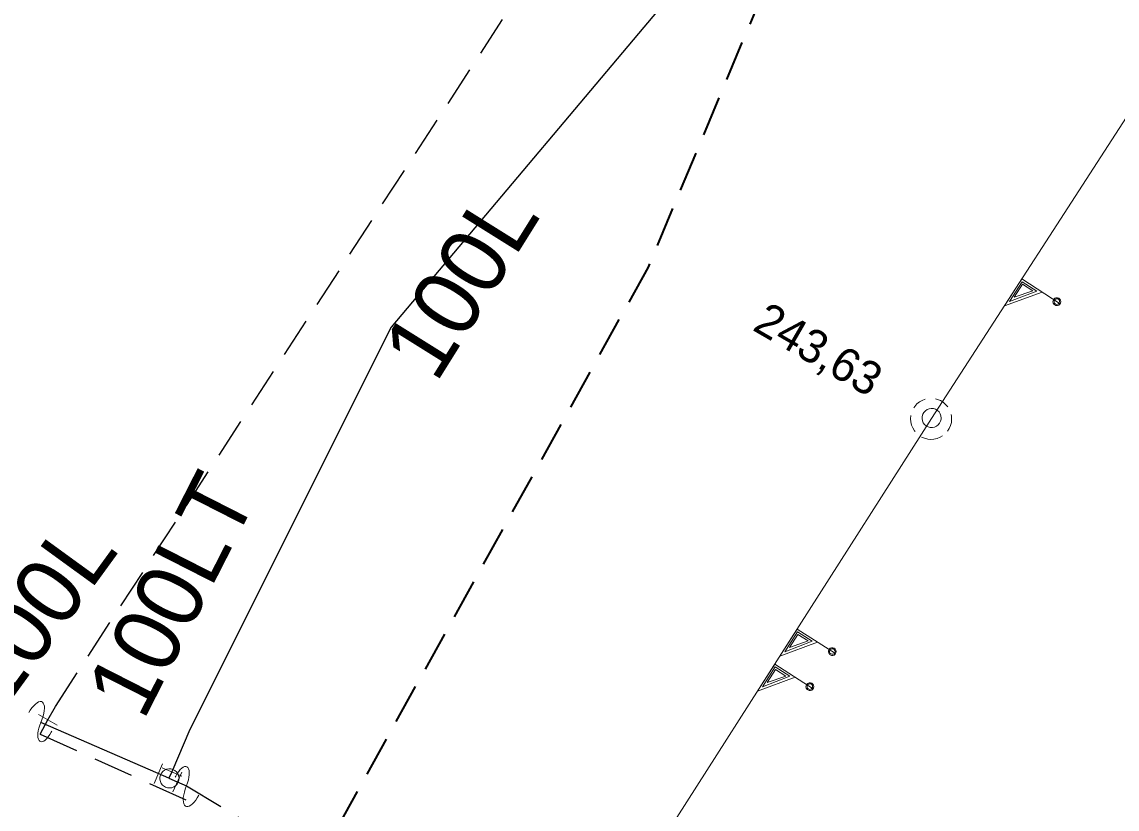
# Model space of a CAD drawing. Extents: x -735085 to -733500, y -1044153 to -1043402.
# Drawn here: x -734690.58 to -734664.28, y -1043609.34 to -1043590.44 of the extents above; entities that cross this region are included whole.
import ezdxf

# ---------------------------------------------------------------- set-up
doc = ezdxf.new("R2010")
doc.units = 0
doc.header["$LTSCALE"] = 0.32
doc.linetypes.add('MEDIUM_DASHED', pattern=[4.5, 3, -1.5])
doc.layers.add('15', color=7, linetype='Continuous')
doc.layers.add('16', color=7, linetype='Continuous')
for name, color, linetype, lineweight in [('18', 7, 'Continuous', 13), ('20', 7, 'Continuous', 13), ('8', 7, 'Continuous', 13)]:
    doc.layers.add(name, color=color, linetype=linetype, lineweight=lineweight)

msp = doc.modelspace()

# ---------------------------------------------------------------- linework, layer by layer
at = {"layer": '18'}
for points in [[(-734665.652, -1043597.204), (-734666.572, -1043596.609), (-734666.99, -1043597.257), (-734666.086, -1043596.923)], [(-734666.214, -1043596.901), (-734666.563, -1043596.675), (-734666.871, -1043597.151), (-734666.212, -1043596.902)], [(-734666.309, -1043596.896), (-734666.554, -1043596.737), (-734666.756, -1043597.049), (-734666.309, -1043596.895)], [(-734668.892, -1043599.497), (-734668.963, -1043599.525), (-734669.029, -1043599.564), (-734669.09, -1043599.612), (-734669.141, -1043599.669), (-734669.164, -1043599.703)], [(-734668.35, -1043599.68), (-734668.401, -1043599.622), (-734668.458, -1043599.572), (-734668.524, -1043599.531), (-734668.595, -1043599.502), (-734668.644, -1043599.488)], [(-734669.237, -1043599.889), (-734669.242, -1043599.966), (-734669.237, -1043600.043), (-734669.22, -1043600.118), (-734669.191, -1043600.189), (-734669.151, -1043600.255), (-734669.136, -1043600.277)], [(-734668.355, -1043600.266), (-734668.315, -1043600.201), (-734668.284, -1043600.131), (-734668.264, -1043600.056), (-734668.257, -1043599.98), (-734668.262, -1043599.903), (-734668.267, -1043599.868)], [(-734668.978, -1043600.406), (-734668.909, -1043600.437), (-734668.833, -1043600.456), (-734668.757, -1043600.463), (-734668.681, -1043600.458), (-734668.605, -1043600.441), (-734668.534, -1043600.413), (-734668.473, -1043600.378)], [(-734671.044, -1043605.608), (-734671.967, -1043605.019), (-734672.382, -1043605.669), (-734671.48, -1043605.33)], [(-734671.607, -1043605.309), (-734671.958, -1043605.085), (-734672.263, -1043605.562), (-734671.606, -1043605.31)], [(-734671.703, -1043605.304), (-734671.949, -1043605.147), (-734672.148, -1043605.46), (-734671.702, -1043605.303)], [(-734671.582, -1043606.451), (-734672.505, -1043605.862), (-734672.92, -1043606.512), (-734672.018, -1043606.173)], [(-734672.145, -1043606.152), (-734672.496, -1043605.928), (-734672.801, -1043606.405), (-734672.144, -1043606.153)], [(-734672.241, -1043606.147), (-734672.487, -1043605.99), (-734672.686, -1043606.303), (-734672.24, -1043606.146)]]:
    msp.add_lwpolyline(points, dxfattribs=at)
for points in [[(-734665.783, -1043597.232), (-734665.752, -1043597.245), (-734665.718, -1043597.247), (-734665.686, -1043597.236), (-734665.661, -1043597.215), (-734665.644, -1043597.187), (-734665.638, -1043597.153), (-734665.643, -1043597.12), (-734665.66, -1043597.091), (-734665.686, -1043597.07), (-734665.719, -1043597.059), (-734665.752, -1043597.061), (-734665.782, -1043597.073), (-734665.807, -1043597.096), (-734665.822, -1043597.126), (-734665.826, -1043597.159), (-734665.817, -1043597.192), (-734665.798, -1043597.22)], [(-734665.77, -1043597.209), (-734665.743, -1043597.219), (-734665.714, -1043597.217), (-734665.69, -1043597.204), (-734665.672, -1043597.181), (-734665.666, -1043597.154), (-734665.67, -1043597.126), (-734665.686, -1043597.103), (-734665.711, -1043597.088), (-734665.739, -1043597.086), (-734665.765, -1043597.093), (-734665.787, -1043597.113), (-734665.799, -1043597.137), (-734665.798, -1043597.166), (-734665.787, -1043597.193)], [(-734668.507, -1043599.949), (-734668.514, -1043599.897), (-734668.531, -1043599.847), (-734668.559, -1043599.803), (-734668.598, -1043599.766), (-734668.642, -1043599.739), (-734668.693, -1043599.723), (-734668.745, -1043599.718), (-734668.796, -1043599.725), (-734668.845, -1043599.744), (-734668.889, -1043599.774), (-734668.924, -1043599.813), (-734668.951, -1043599.858), (-734668.965, -1043599.909), (-734668.968, -1043599.961), (-734668.96, -1043600.013), (-734668.94, -1043600.061), (-734668.909, -1043600.104), (-734668.87, -1043600.139), (-734668.823, -1043600.163), (-734668.772, -1043600.177), (-734668.72, -1043600.179), (-734668.669, -1043600.169), (-734668.62, -1043600.147), (-734668.578, -1043600.115), (-734668.546, -1043600.075), (-734668.522, -1043600.028), (-734668.509, -1043599.977)], [(-734671.174, -1043605.638), (-734671.143, -1043605.651), (-734671.11, -1043605.652), (-734671.078, -1043605.641), (-734671.052, -1043605.62), (-734671.035, -1043605.591), (-734671.03, -1043605.558), (-734671.035, -1043605.525), (-734671.053, -1043605.496), (-734671.078, -1043605.475), (-734671.111, -1043605.465), (-734671.144, -1043605.466), (-734671.175, -1043605.479), (-734671.199, -1043605.502), (-734671.214, -1043605.532), (-734671.218, -1043605.565), (-734671.209, -1043605.598), (-734671.19, -1043605.625)], [(-734671.161, -1043605.614), (-734671.134, -1043605.624), (-734671.106, -1043605.622), (-734671.081, -1043605.609), (-734671.064, -1043605.586), (-734671.058, -1043605.559), (-734671.062, -1043605.531), (-734671.078, -1043605.508), (-734671.103, -1043605.493), (-734671.131, -1043605.491), (-734671.158, -1043605.499), (-734671.18, -1043605.518), (-734671.191, -1043605.543), (-734671.19, -1043605.572), (-734671.179, -1043605.598)], [(-734671.712, -1043606.481), (-734671.681, -1043606.494), (-734671.648, -1043606.495), (-734671.616, -1043606.484), (-734671.59, -1043606.463), (-734671.573, -1043606.434), (-734671.568, -1043606.401), (-734671.573, -1043606.368), (-734671.591, -1043606.339), (-734671.616, -1043606.318), (-734671.649, -1043606.308), (-734671.682, -1043606.309), (-734671.713, -1043606.322), (-734671.737, -1043606.345), (-734671.752, -1043606.375), (-734671.756, -1043606.408), (-734671.747, -1043606.441), (-734671.728, -1043606.468)], [(-734671.699, -1043606.457), (-734671.672, -1043606.467), (-734671.644, -1043606.465), (-734671.619, -1043606.452), (-734671.602, -1043606.429), (-734671.596, -1043606.402), (-734671.6, -1043606.374), (-734671.616, -1043606.351), (-734671.641, -1043606.336), (-734671.669, -1043606.334), (-734671.696, -1043606.342), (-734671.718, -1043606.361), (-734671.729, -1043606.386), (-734671.728, -1043606.415), (-734671.717, -1043606.441)]]:
    msp.add_lwpolyline(points, close=True, dxfattribs=at)
at = {"layer": '20'}
for p, q in [((-734652.84, -1043575.36), (-734668.739, -1043599.96)), ((-734652.84, -1043575.36), (-734668.739, -1043599.96)), ((-734668.739, -1043599.96), (-734684.89, -1043625.26)), ((-734668.739, -1043599.96), (-734684.89, -1043625.26))]:
    msp.add_line(p, q, dxfattribs=at)
at = {"layer": '8'}
for p, q in [((-734690.186, -1043607.073), (-734689.735, -1043607.325)), ((-734687.41, -1043608.728), (-734687.208, -1043608.252)), ((-734686.74, -1043608.55), (-734687.217, -1043608.349)), ((-734686.743, -1043608.453), (-734686.955, -1043608.924))]:
    msp.add_line(p, q, dxfattribs=at)
at = {"layer": '8', "linetype": 'MEDIUM_DASHED', "lineweight": 25}
for p, q in [((-734690.147, -1043607.545), (-734689.96, -1043607.2)), ((-734690.147, -1043607.545), (-734686.631, -1043609.123)), ((-734686.629, -1043608.78), (-734684.458, -1043610.098))]:
    msp.add_line(p, q, dxfattribs=at)
at = {"layer": '8', "lineweight": 25}
for p, q in [((-734687.05, -1043608.6), (-734686.85, -1043608.69)), ((-734686.85, -1043608.69), (-734686.629, -1043608.78))]:
    msp.add_line(p, q, dxfattribs=at)
at = {"layer": '8', "linetype": 'MEDIUM_DASHED', "lineweight": 35}
msp.add_lwpolyline([(-734668.849, -1043580.305), (-734675.546, -1043596.328), (-734683.508, -1043610.677), (-734694.054, -1043642.408), (-734687.381, -1043651.433), (-734629.763, -1043729.041), (-734628.401, -1043750.135), (-734626.521, -1043774.035)], dxfattribs=at)
at = {"layer": '8', "linetype": 'MEDIUM_DASHED', "lineweight": 25}
msp.add_lwpolyline([(-734689.96, -1043607.2), (-734689.776, -1043606.875), (-734675.289, -1043584.62)], dxfattribs=at)
at = {"layer": '8', "lineweight": 25}
for points in [[(-734675.239, -1043585.31), (-734674.41, -1043589.08), (-734681.719, -1043597.77), (-734686.55, -1043607.43), (-734686.98, -1043608.45)], [(-734686.98, -1043608.45), (-734687.05, -1043608.6), (-734687.309, -1043608.49), (-734690.129, -1043607.26)]]:
    msp.add_lwpolyline(points, dxfattribs=at)
at = {"layer": '8'}
for points in [[(-734690.417, -1043607.025), (-734690.38, -1043606.963), (-734690.34, -1043606.907), (-734690.299, -1043606.858), (-734690.258, -1043606.818), (-734690.218, -1043606.788), (-734690.181, -1043606.767), (-734690.146, -1043606.757), (-734690.115, -1043606.759), (-734690.089, -1043606.771), (-734690.068, -1043606.795), (-734690.052, -1043606.827), (-734690.043, -1043606.869), (-734690.041, -1043606.921), (-734690.045, -1043606.978), (-734690.056, -1043607.041), (-734690.072, -1043607.108), (-734690.095, -1043607.176), (-734690.122, -1043607.245), (-734690.132, -1043607.264)], [(-734690.129, -1043607.262), (-734690.155, -1043607.328), (-734690.175, -1043607.395), (-734690.189, -1043607.459), (-734690.199, -1043607.521), (-734690.201, -1043607.575), (-734690.197, -1043607.624), (-734690.186, -1043607.664), (-734690.171, -1043607.694), (-734690.149, -1043607.714), (-734690.122, -1043607.723), (-734690.092, -1043607.721), (-734690.059, -1043607.707), (-734690.023, -1043607.683), (-734689.985, -1043607.649), (-734689.948, -1043607.606), (-734689.911, -1043607.554), (-734689.876, -1043607.497), (-734689.862, -1043607.47)], [(-734686.628, -1043608.777), (-734686.603, -1043608.71), (-734686.585, -1043608.643), (-734686.572, -1043608.578), (-734686.564, -1043608.517), (-734686.563, -1043608.462), (-734686.568, -1043608.413), (-734686.58, -1043608.374), (-734686.596, -1043608.344), (-734686.619, -1043608.325), (-734686.645, -1043608.316), (-734686.676, -1043608.319), (-734686.709, -1043608.333), (-734686.743, -1043608.358), (-734686.781, -1043608.394), (-734686.817, -1043608.437), (-734686.852, -1043608.49), (-734686.886, -1043608.548), (-734686.899, -1043608.575)], [(-734686.335, -1043609.007), (-734686.37, -1043609.07), (-734686.409, -1043609.127), (-734686.449, -1043609.177), (-734686.489, -1043609.217), (-734686.528, -1043609.249), (-734686.565, -1043609.271), (-734686.599, -1043609.281), (-734686.63, -1043609.281), (-734686.657, -1043609.269), (-734686.679, -1043609.246), (-734686.695, -1043609.213), (-734686.705, -1043609.171), (-734686.708, -1043609.12), (-734686.706, -1043609.063), (-734686.696, -1043609), (-734686.681, -1043608.932), (-734686.66, -1043608.863), (-734686.634, -1043608.794), (-734686.625, -1043608.775)]]:
    msp.add_lwpolyline(points, dxfattribs=at)
msp.add_lwpolyline([(-734687.138, -1043608.813), (-734687.088, -1043608.83), (-734687.035, -1043608.835), (-734686.983, -1043608.828), (-734686.934, -1043608.809), (-734686.89, -1043608.78), (-734686.855, -1043608.741), (-734686.828, -1043608.696), (-734686.812, -1043608.646), (-734686.809, -1043608.594), (-734686.818, -1043608.541), (-734686.838, -1043608.493), (-734686.868, -1043608.45), (-734686.908, -1043608.415), (-734686.954, -1043608.39), (-734687.004, -1043608.376), (-734687.056, -1043608.374), (-734687.108, -1043608.383), (-734687.157, -1043608.405), (-734687.198, -1043608.436), (-734687.232, -1043608.477), (-734687.256, -1043608.523), (-734687.269, -1043608.574), (-734687.269, -1043608.627), (-734687.258, -1043608.679), (-734687.236, -1043608.726), (-734687.203, -1043608.767), (-734687.162, -1043608.8)], close=True, dxfattribs=at)

# ---------------------------------------------------------------- texts
at = {"layer": '15'}
for s, rotation, p in [('100L', 58, (-734680.637, -1043599.134)), ('100LT ', 63, (-734687.667, -1043607.244)), ('100L', 54, (-734691.037, -1043606.995))]:
    msp.add_text(s, height=1.6, rotation=rotation, dxfattribs=at).set_placement(p)
at = {"layer": '16'}
msp.add_text('243,63', height=0.8, rotation=330, dxfattribs=at).set_placement((-734673.068, -1043597.823))

doc.saveas('drawing.dxf')
